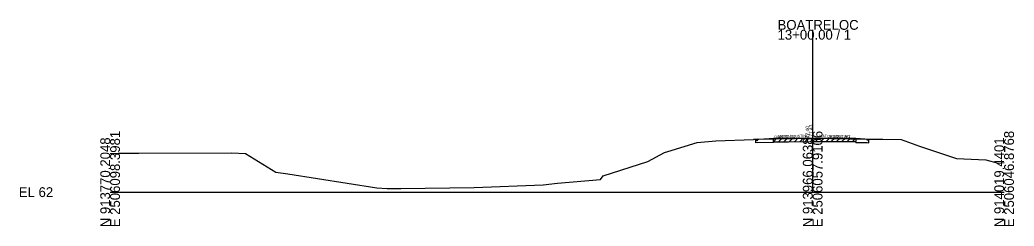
# Model space of a CAD drawing. Extents: x -26 to 403, y -10 to 2549.
# Drawn here: x -25.7 to 257.3, y 1990.3 to 2049.1 of the extents above; entities that cross this region are included whole.
import ezdxf

# ---------------------------------------------------------------- set-up
doc = ezdxf.new("R2010")
doc.units = 0
for name, color, linetype in [('RD_GPK_XS_Cell', 7, 'Continuous'), ('RD_Sketch9', 7, 'Continuous'), ('RD_XS_ExGround', 7, 'Continuous'), ('RD_XS_ExPaveRet', 7, 'Continuous'), ('RD_XS_PaveOvlay', 7, 'Continuous'), ('RD_XS_TX_Elev_EX', 7, 'Continuous'), ('RD_XS_TX_Elev_PR', 7, 'Continuous'), ('RD_XS_TX_Slope', 7, 'Continuous')]:
    doc.layers.add(name, color=color, linetype=linetype)

msp = doc.modelspace()

# ---------------------------------------------------------------- linework, layer by layer
at = {"layer": 'RD_GPK_XS_Cell'}
for p, q in [((200, 2000), (200, 2046.3)), ((0, 2000), (200, 2000)), ((200, 2000), (254.5, 2000))]:
    msp.add_line(p, q, dxfattribs=at)
at = {"layer": 'RD_Sketch9'}
for p, q in [((184.35, 2015.12), (200, 2015.43)), ((200, 2015.43), (215.5, 2015.12)), ((184.35, 2015.12), (183.19, 2015.06)), ((183.85, 2014.78), (184.35, 2014.79)), ((183.85, 2014.11), (183.85, 2014.78)), ((184.35, 2014.12), (183.85, 2014.11)), ((184.35, 2014.79), (184.35, 2015.12)), ((184.35, 2014.12), (188.81, 2014.21)), ((188.81, 2014.21), (188.81, 2014.38)), ((212.32, 2014.19), (212.32, 2014.43)), ((212.32, 2014.19), (215.5, 2014.12)), ((215.5, 2015.12), (220.01, 2015.08)), ((215.5, 2014.79), (215.5, 2015.12)), ((216, 2014.78), (215.5, 2014.79)), ((215.5, 2014.12), (216, 2014.11)), ((216, 2014.11), (216, 2014.78))]:
    msp.add_line(p, q, dxfattribs=at)
at = {"layer": 'RD_XS_ExGround'}
for p, q in [((183.19, 2015.06), (187.58, 2015.31)), ((187.58, 2015.31), (188.81, 2015.38)), ((188.81, 2015.38), (193.13, 2015.38)), ((193.13, 2015.38), (200, 2015.4)), ((200, 2015.4), (212.32, 2015.43)), ((212.32, 2015.43), (214.83, 2015.18)), ((158.72, 2011.6), (167.15, 2014.13)), ((167.15, 2014.13), (172.43, 2014.67)), ((172.43, 2014.67), (183.19, 2015.06)), ((214.83, 2015.18), (225.19, 2014.97)), ((225.19, 2014.97), (230.39, 2013.1)), ((230.39, 2013.1), (240.96, 2009.56)), ((0, 2011.06), (2.24, 2011.09)), ((2.24, 2011.09), (8.18, 2011.12)), ((8.18, 2011.12), (34.66, 2011.24)), ((34.66, 2011.24), (38.54, 2010.99)), ((38.54, 2010.99), (47.19, 2005.72)), ((153.03, 2008.7), (157.85, 2011.27)), ((157.85, 2011.27), (158.72, 2011.6)), ((140.36, 2004.63), (153.03, 2008.7)), ((240.96, 2009.56), (249.29, 2009.23)), ((249.29, 2009.23), (252.85, 2008.28)), ((252.85, 2008.28), (254.5, 2008.48)), ((47.19, 2005.72), (50.56, 2005.23)), ((50.56, 2005.23), (75.9, 2001.21)), ((139.58, 2003.58), (140.36, 2004.63)), ((75.9, 2001.21), (78.91, 2001.04)), ((82.74, 2001.04), (103.65, 2001.35)), ((103.65, 2001.35), (123.27, 2002.05)), ((123.27, 2002.05), (127.31, 2002.55)), ((127.31, 2002.55), (139.58, 2003.58)), ((78.91, 2001.04), (82.74, 2001.04))]:
    msp.add_line(p, q, dxfattribs=at)
at = {"layer": 'RD_XS_ExPaveRet'}
for p, q in [((188.81, 2014.38), (189.81, 2015.38)), ((188.81, 2014.38), (188.81, 2015.38)), ((190.31, 2014.38), (191.31, 2015.38)), ((191.81, 2014.38), (192.81, 2015.38)), ((193.31, 2014.38), (194.31, 2015.38)), ((194.81, 2014.38), (195.81, 2015.38)), ((196.31, 2014.38), (197.31, 2015.39)), ((197.81, 2014.39), (198.81, 2015.39)), ((199.31, 2014.39), (200.31, 2015.4)), ((200.81, 2014.4), (201.81, 2015.4)), ((202.31, 2014.4), (203.31, 2015.41)), ((203.81, 2014.41), (204.81, 2015.41)), ((205.31, 2014.41), (206.31, 2015.41)), ((206.81, 2014.42), (207.81, 2015.42)), ((208.31, 2014.42), (209.31, 2015.42)), ((209.81, 2014.42), (210.81, 2015.43)), ((211.31, 2014.43), (212.31, 2015.43)), ((212.32, 2015.43), (212.32, 2014.43)), ((188.81, 2014.38), (193.13, 2014.38)), ((193.13, 2014.38), (200, 2014.4)), ((200, 2014.4), (212.32, 2014.43))]:
    msp.add_line(p, q, dxfattribs=at)
at = {"layer": 'RD_XS_PaveOvlay'}
for p, q in [((188.81, 2015.38), (200, 2015.43)), ((200, 2015.43), (212.32, 2015.43))]:
    msp.add_line(p, q, dxfattribs=at)

# ---------------------------------------------------------------- texts
at = {"layer": 'RD_GPK_XS_Cell'}
for s, p in [('13+00.00 / 1', (190, 2043.5)), ('BOATRELOC', (190, 2046.3)), ('EL 62', (-26, 1998.6))]:
    msp.add_text(s, height=2.8, dxfattribs=at).set_placement(p)
for s, p in [('N 913770.2048', (0, 1990)), ('E 2506098.3981', (2.8, 1990)), ('N 913966.0638', (200, 1990)), ('E 2506057.9106', (202.8, 1990)), ('N 914019.4401', (254.5, 1990)), ('E 2506046.8768', (257.3, 1990))]:
    msp.add_text(s, height=2.8, rotation=90, dxfattribs=at).set_placement(p)
at = {"layer": 'RD_Sketch9'}
for s, height, rotation, p in [(' 77.43', 1, 90, (200, 2015.43)), (' 77.43', 1, 90, (200, 2015.43)), ('0.020 FT./FT.', 0.75, 1.1458, (189.14, 2015.47)), ('0.020 FT./FT.', 0.75, 358.8542, (204.73, 2015.59))]:
    msp.add_text(s, height=height, rotation=rotation, dxfattribs=at).set_placement(p)
at = {"layer": 'RD_XS_TX_Elev_EX'}
msp.add_text('77.40', height=1, rotation=90, dxfattribs=at).set_placement((199, 2015.4))
at = {"layer": 'RD_XS_TX_Elev_PR'}
msp.add_text(' 77.43', height=1, rotation=90, dxfattribs=at).set_placement((200, 2015.43))
at = {"layer": 'RD_XS_TX_Slope'}
for rotation, p in [(1.1458, (190.12, 2015.48)), (358.8542, (201.89, 2015.64))]:
    msp.add_text('MATCH EXISTING', height=0.75, rotation=rotation, dxfattribs=at).set_placement(p)

doc.saveas('drawing.dxf')
